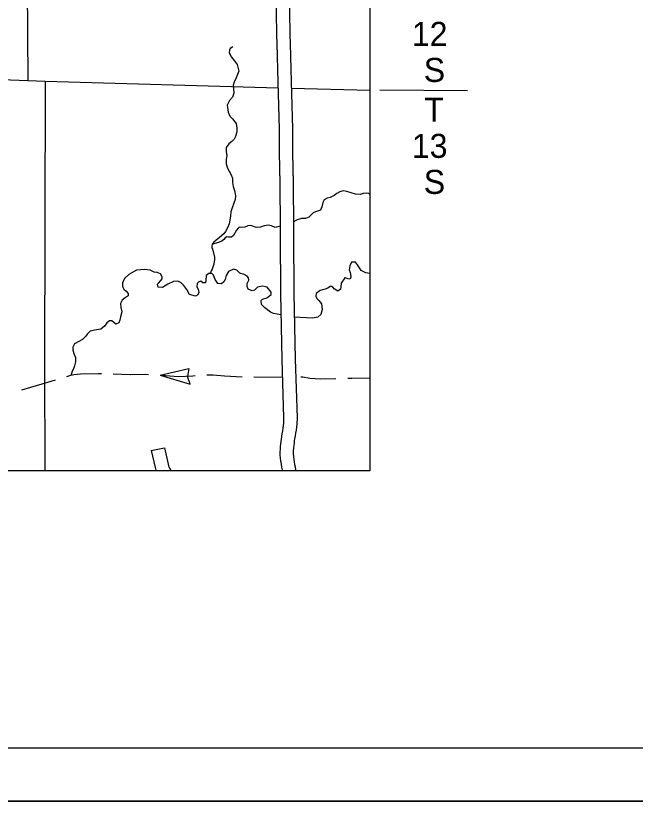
# Model space of a CAD drawing. Extents: x 1373094 to 1376427, y 1168361 to 1170494.
# Drawn here: x 1375232 to 1375696, y 1168361 to 1168950 of the extents above; entities that cross this region are included whole.
import ezdxf

# ---------------------------------------------------------------- set-up
doc = ezdxf.new("R2010")
doc.units = 0
for name, color, linetype in [('Default', 7, 'Continuous'), ('R_Axis', 7, 'Continuous'), ('R_Border', 7, 'Continuous'), ('R_No Plot', 7, 'Continuous'), ('R_Water Annot', 7, 'Continuous')]:
    doc.layers.add(name, color=color, linetype=linetype)

msp = doc.modelspace()

# ---------------------------------------------------------------- linework, layer by layer
at = {"layer": 'R_Axis'}
for p, q in [((1375339.82, 1168680.21), (1375361.47, 1168685.31)), ((1375361.47, 1168685.31), (1375360.29, 1168679.33)), ((1375339.82, 1168680.21), (1375362.26, 1168673.49)), ((1375362.26, 1168673.49), (1375360.3, 1168679.25)), ((1375333.26, 1168623.73), (1375343.02, 1168625.89))]:
    msp.add_line(p, q, dxfattribs=at)
for points in [[(1375237.22, 1169372.94), (1375238.19, 1169252.01), (1375240.86, 1168901.02)], [(1375427.37, 1168935.13), (1375426.86, 1168970.32)], [(1375437.36, 1168935.27), (1375436.86, 1168970.47)], [(1375428.24, 1168899.88), (1375427.46, 1168928.69), (1375427.37, 1168935.13)], [(1375438.23, 1168900.15), (1375437.46, 1168928.89), (1375437.36, 1168935.27)], [(1375394.23, 1168926.32), (1375392.39, 1168924.96), (1375391.75, 1168923.88), (1375391.65, 1168921.74), (1375393.24, 1168918.43), (1375395.2, 1168916.12), (1375397.58, 1168913.08), (1375398.73, 1168908.02), (1375396.76, 1168902.98), (1375395.28, 1168899.82), (1375394.65, 1168897.54), (1375394.9, 1168895), (1375395.08, 1168891.67), (1375394.01, 1168888.58), (1375391.85, 1168886.14), (1375390.05, 1168882.5), (1375390.74, 1168877.31), (1375392.12, 1168874.39), (1375394.01, 1168872.41), (1375396.74, 1168868.78), (1375397.19, 1168865.65), (1375397.24, 1168862.71), (1375396.23, 1168859.15), (1375395.2, 1168857.2), (1375393.5, 1168855.44), (1375391.4, 1168853.54), (1375389.19, 1168850.76), (1375389.3, 1168847.82), (1375389.82, 1168844.63), (1375389.34, 1168842.01), (1375389.26, 1168838.67), (1375390.25, 1168835.41), (1375392.78, 1168830.91), (1375394.03, 1168827.99), (1375394.09, 1168824.52), (1375394.47, 1168821.65), (1375395.59, 1168818.6), (1375396.19, 1168814.53), (1375395.97, 1168811.86), (1375395.08, 1168809.24), (1375393.74, 1168805.61), (1375392.73, 1168802.72), (1375392.45, 1168799.58), (1375392.17, 1168796.3), (1375391.48, 1168793.68), (1375390.34, 1168790.66), (1375388.85, 1168787.9), (1375387.62, 1168786.28), (1375384.27, 1168783.42), (1375381.84, 1168781.51), (1375379.81, 1168779.74), (1375378.83, 1168778.26), (1375378.58, 1168777.18), (1375378.68, 1168775.78), (1375378.96, 1168774.92)], [(1374799.62, 1168916.14), (1374903.5, 1168913.86), (1374921.14, 1168913.33), (1375240.86, 1168901.02), (1375253.71, 1168900.55), (1375428.35, 1168895.68)], [(1375253.71, 1168900.55), (1375253.19, 1168687.12)], [(1375429.19, 1168864.69), (1375428.24, 1168899.88)], [(1375439.18, 1168864.96), (1375438.23, 1168900.15)], [(1375438.36, 1168895.41), (1375496.95, 1168893.83)], [(1375429.47, 1168829.58), (1375429.27, 1168852.84), (1375429.23, 1168863.01), (1375429.19, 1168864.69)], [(1375439.47, 1168829.67), (1375439.27, 1168852.9), (1375439.23, 1168863.16), (1375439.18, 1168864.96)], [(1375429.47, 1168829.58), (1375430.03, 1168741.33), (1375430.99, 1168692.05)], [(1375439.47, 1168829.67), (1375440.03, 1168741.46), (1375440.99, 1168692.3)], [(1375496.95, 1168815.65), (1375496.05, 1168816.36), (1375494.25, 1168816.73), (1375491.99, 1168816.36), (1375489.67, 1168815.72), (1375486.27, 1168816), (1375482.87, 1168816.82), (1375479.72, 1168817.84), (1375477.05, 1168818.4), (1375474.4, 1168817.76), (1375472.29, 1168816.32), (1375470.18, 1168815.02), (1375467.28, 1168813.37), (1375464.96, 1168813), (1375462.79, 1168811.76), (1375461.62, 1168809.67), (1375461.01, 1168806.53), (1375459.99, 1168803.97), (1375456.35, 1168802.65), (1375454.37, 1168802.01), (1375452.8, 1168800.12), (1375451.3, 1168798.56), (1375448.72, 1168797.65), (1375445.72, 1168797.74), (1375442.61, 1168796.75), (1375439.68, 1168795.26)], [(1375420.85, 1168792.74), (1375417.86, 1168792.29), (1375415.09, 1168791.11), (1375411.76, 1168790.86), (1375409.35, 1168791.83), (1375407.88, 1168792.4), (1375405.48, 1168792.23), (1375403.37, 1168791.13), (1375400.32, 1168790.88), (1375399.11, 1168791.2), (1375398.39, 1168790.32), (1375397.16, 1168788.83), (1375394.76, 1168784.92), (1375393.38, 1168783.76), (1375391.12, 1168783.79), (1375389.92, 1168784.04), (1375388.6, 1168783.22), (1375387.49, 1168781.87), (1375386.11, 1168780.78), (1375384.46, 1168780.15), (1375383.47, 1168779.8), (1375378.96, 1168778.46)], [(1375429.71, 1168791.88), (1375426.07, 1168790.95), (1375423.19, 1168792.11), (1375420.85, 1168792.74)], [(1375378.96, 1168774.92), (1375380.52, 1168768.73), (1375380.62, 1168766.86), (1375380.08, 1168763.45), (1375379.51, 1168761.84), (1375378.75, 1168759.75), (1375378.1, 1168758.47), (1375377.78, 1168757.73), (1375377.46, 1168757.13), (1375377.09, 1168756.44)], [(1375430.34, 1168725.42), (1375424.83, 1168726.6), (1375422.55, 1168727.44), (1375418.17, 1168730.64), (1375415.86, 1168733.28), (1375415.55, 1168736.15), (1375416.59, 1168737.3), (1375419.84, 1168738.15), (1375423.06, 1168740.67), (1375422.96, 1168742.41), (1375420.04, 1168746.1), (1375416.56, 1168746.92), (1375412.72, 1168746.19), (1375410.49, 1168744.08), (1375408.77, 1168743.39), (1375405.89, 1168744.68), (1375405.05, 1168746.8), (1375405.08, 1168749.07), (1375406.3, 1168751.5), (1375406.01, 1168753.23), (1375404.99, 1168754.55), (1375402.84, 1168755.65), (1375399.63, 1168756.74), (1375397.19, 1168759.04), (1375394.72, 1168759.67), (1375391.02, 1168757.87), (1375389.41, 1168755.04), (1375388.53, 1168751.96), (1375387.69, 1168750.14), (1375385.86, 1168748.64), (1375383.19, 1168748.93), (1375381.14, 1168751.84), (1375379.82, 1168755.16), (1375378.47, 1168756.54), (1375376.27, 1168756.37), (1375374.43, 1168755.01), (1375374.16, 1168751.26), (1375373.73, 1168749.52), (1375371.93, 1168749.36), (1375370.32, 1168750.6), (1375368.92, 1168750.31), (1375367.62, 1168748.96), (1375367.46, 1168746.48), (1375368.29, 1168744.63), (1375368.79, 1168742.16), (1375368.16, 1168740.48), (1375366.25, 1168739.45), (1375361.96, 1168740.72), (1375359.77, 1168744.36), (1375357.73, 1168747.4), (1375355.69, 1168749.57), (1375353.08, 1168750.8), (1375349.89, 1168750.42), (1375345.73, 1168748.35), (1375341.71, 1168745.95), (1375338.31, 1168746.23), (1375337.81, 1168748.36), (1375338.73, 1168749.31), (1375340.36, 1168751.14), (1375341.27, 1168752.49), (1375341.31, 1168753.89), (1375340.14, 1168756.21), (1375337.66, 1168757.24), (1375335.46, 1168757.47), (1375332.31, 1168758.96), (1375328.17, 1168759.56), (1375322.19, 1168758.87), (1375316.39, 1168755.71), (1375313.38, 1168752.92), (1375311.76, 1168749.82), (1375311.68, 1168746.68), (1375312.72, 1168744.76), (1375314.34, 1168743.32), (1375316.03, 1168741.54), (1375315.8, 1168739.67), (1375313.76, 1168738.16), (1375311.46, 1168736.39), (1375310.1, 1168733.97), (1375310.42, 1168730.97), (1375311.14, 1168727.84), (1375310.27, 1168724.08)], [(1375496.95, 1168756.46), (1375493.92, 1168757.07), (1375490.44, 1168758.62), (1375489.14, 1168760.61), (1375487.63, 1168763.05), (1375486.14, 1168764.9), (1375483.08, 1168764.92), (1375481.92, 1168762.3), (1375481.44, 1168759.15), (1375482.14, 1168757.22), (1375482.65, 1168754.56), (1375482.35, 1168752.68), (1375481.09, 1168752.26), (1375478.68, 1168753.09), (1375478.15, 1168753.09), (1375475.42, 1168749.1), (1375475.2, 1168746.43), (1375474.9, 1168744.69), (1375472.99, 1168743.32), (1375470.1, 1168745.01), (1375469.56, 1168745.87), (1375468.28, 1168746.72), (1375467.28, 1168746.7), (1375465.57, 1168745.54), (1375463.52, 1168744.64)], [(1375463.52, 1168744.64), (1375461.46, 1168744.34), (1375459.74, 1168743.71), (1375456.72, 1168741.4), (1375456.42, 1168739.39), (1375457.18, 1168737.6), (1375458.74, 1168736.28), (1375460.64, 1168733.78), (1375461.25, 1168729.58), (1375460.31, 1168725.75), (1375458.08, 1168723.78), (1375453.97, 1168722.98), (1375440.37, 1168723.76)], [(1375310.27, 1168724.08), (1375309.71, 1168721.54), (1375309.02, 1168719.39), (1375306.71, 1168718.42), (1375303.67, 1168720.91), (1375301.87, 1168721.08), (1375299.83, 1168719.44), (1375298.28, 1168716.88), (1375295.32, 1168714.63), (1375290.61, 1168714.02), (1375287.42, 1168713.37), (1375285.27, 1168711.07), (1375284.3, 1168709.38), (1375281.68, 1168706.94), (1375278.9, 1168705.56), (1375275.81, 1168703.84), (1375274.52, 1168701.28), (1375274.42, 1168699.21), (1375275.26, 1168696.48), (1375276.38, 1168693.49), (1375276.5, 1168690.22), (1375275.82, 1168687.34), (1375274.86, 1168685.12), (1375274.09, 1168683.37), (1375273.59, 1168681.63), (1375273.03, 1168680.02)], [(1375430.99, 1168692.05), (1375432.36, 1168648.38), (1375432.24, 1168644.31), (1375431.74, 1168640.53), (1375431.42, 1168638.46), (1375431.08, 1168636.38), (1375430.75, 1168634.23), (1375430.45, 1168632.39), (1375430.23, 1168630.5), (1375430, 1168628.71), (1375429.86, 1168626.62), (1375429.65, 1168624.56), (1375429.54, 1168623.06), (1375429.53, 1168620.64), (1375429.82, 1168618.21), (1375429.96, 1168615.98), (1375430.39, 1168613.63), (1375430.73, 1168611.45), (1375431.15, 1168609.46), (1375431.34, 1168608.52)], [(1375440.99, 1168692.3), (1375442.37, 1168648.39), (1375442.22, 1168643.51), (1375441.64, 1168639.11), (1375441.3, 1168636.89), (1375440.96, 1168634.81), (1375440.62, 1168632.66), (1375440.36, 1168631.01), (1375440.16, 1168629.28), (1375439.96, 1168627.72), (1375439.82, 1168625.79), (1375439.62, 1168623.7), (1375439.54, 1168622.66), (1375439.53, 1168621.21), (1375439.78, 1168619.11), (1375439.9, 1168617.21), (1375440.25, 1168615.31), (1375440.57, 1168613.24), (1375440.94, 1168611.51), (1375441.35, 1168609.5), (1375441.5, 1168608.52)], [(1375253.19, 1168687.12), (1375253.37, 1168608.52)], [(1375295.85, 1168681.24), (1375293.79, 1168681.3), (1375280.17, 1168680.96), (1375275.26, 1168680.41), (1375271.95, 1168679.84), (1375269.64, 1168679.13)], [(1375317.84, 1168680.62), (1375317.57, 1168680.62), (1375304.64, 1168680.99)], [(1375331.03, 1168680.64), (1375329.01, 1168680.77), (1375317.84, 1168680.62)], [(1375366.15, 1168679.69), (1375364.31, 1168679.57), (1375358.93, 1168679.2), (1375353.61, 1168679.04), (1375347.21, 1168679.58), (1375340.67, 1168680.05), (1375339.81, 1168680.1)], [(1375401.28, 1168678.81), (1375401.19, 1168678.81), (1375387.99, 1168679.62), (1375379.65, 1168680.37), (1375374.94, 1168680.18)], [(1375431.41, 1168678.62), (1375410.08, 1168678.76)], [(1375471.58, 1168677.58), (1375459.85, 1168677.39), (1375451.99, 1168677.75), (1375446.84, 1168678.66), (1375445.27, 1168678.73)], [(1375496.95, 1168677.93), (1375483.39, 1168677.77), (1375480.38, 1168677.72)], [(1375261.25, 1168676.46), (1375258.1, 1168675.55), (1375235.91, 1168669.07)], [(1375343.02, 1168625.89), (1375345.76, 1168613.49), (1375346.09, 1168612.33), (1375346.25, 1168611.93), (1375346.93, 1168610.62), (1375347.67, 1168609.41), (1375348.34, 1168608.52)], [(1375333.26, 1168623.73), (1375336.06, 1168611.06), (1375336.63, 1168609.04), (1375336.84, 1168608.52)]]:
    msp.add_lwpolyline(points, dxfattribs=at)
at = {"layer": 'R_Border'}
msp.add_line((1376379.55, 1168400.82), (1373217.75, 1168400.82), dxfattribs=at)
at = {"layer": 'R_No Plot'}
msp.add_line((1373093.74, 1168361.03), (1376427.07, 1168361.03), dxfattribs=at)
for points in [[(1373093.67, 1170494.36), (1376427.07, 1170494.36), (1376427.07, 1168360.99), (1373093.67, 1168360.99)], [(1373989.53, 1169534.16), (1375496.95, 1169534.16), (1375496.95, 1168608.52), (1373989.53, 1168608.52)]]:
    msp.add_lwpolyline(points, close=True, dxfattribs=at)
at = {"layer": 'R_Water Annot'}
msp.add_line((1375570.2, 1168893.31), (1375504.4, 1168893.83), dxfattribs=at)

# ---------------------------------------------------------------- texts
at = {"layer": 'Default'}
for s, p in [('12', (1375528.34, 1168926.98)), ('S', (1375537.29, 1168899.98)), ('T', (1375537.67, 1168870.1)), ('13', (1375528.33, 1168843.1)), ('S', (1375537.29, 1168816.1))]:
    msp.add_text(s, height=18, dxfattribs=at).set_placement(p)

doc.saveas('drawing.dxf')
